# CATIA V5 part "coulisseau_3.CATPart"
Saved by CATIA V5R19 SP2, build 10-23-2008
Part number: coulisseau_3
Bounding box of the stored display mesh (mm): x -14.734 to 15.006, y -10 to 10, z -13.975 to 13.961
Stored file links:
  D:\Dropbox\IAO_2011\MMS_GR2\IAO_2011_1492_afeiguel\IAO_2011_1492_afeiguel\coulisseau_3.CATPart
  C:\Users\Nono\Desktop\projets ifma\IAO finis\assemblage_IAO.CATProduct
  D:\Dropbox\IAO_2011\MMS_GR2\IAO_2011_1492_afeiguel\IAO_2011_1492_afeiguel\bati_0.CATPart
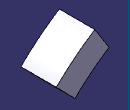
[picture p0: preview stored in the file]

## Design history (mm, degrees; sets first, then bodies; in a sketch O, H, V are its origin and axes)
External parameters (linked from other documents)
  External.e_rainure = 15 mm
  `External.rayon_glissière` = 125 mm
  `External.épaisseur` = 20 mm
Set1
  DatumSurface1: linked copy from another document
Body1 (main body)
  Sketch1 on yz-plane, origin (0, 0, 0), H (0, 1, 0), V (0, 0, 1)
    point P1 (0, 0)
    line L1 (-70.373, 0) -> (70, 0)
    point P2 (-70.373, 0)
    coincidence: P1 O, P2 H
    horizontal: L1 H
  Sketch2 on face of DatumSurface1, origin (0, -10, 0), H (1, 0, 0), V (0, 0, 1)
    arc A1 centre (-77.813, -97.8271) radius 132.5 from (15.006, -3.2708) to (-6.6817, 13.9611) ccw
    point P2 (-77.813, -97.8271)
    line L1 (15.006, -3.2708) -> (4.4982, -13.9753)
    line L2 (-6.6817, 13.9611) -> (-14.7343, 1.3058)
    arc A2 centre (-77.813, -97.8271) radius 117.5 from (4.4982, -13.9753) to (-14.7343, 1.3058) ccw
    point P6 (-77.813, -97.8271)
    reference projected point E1 (0, 0) from Sketch1.P1
    reference projected point E2 (0, 0) from Sketch1.P1
    reference projected point E3 (0, 0) from Sketch1.L1
    length L2 = 15 {= External.e_rainure}
    angle L1 L2 = 12
    distance P6 E1 = 125 {= `External.rayon_glissière`}
    distance E2 L1 = 13
    distance E3 A1 = 7.5 {= External.e_rainure /2}
    coincidence: L1 P2, L2 P2, P6 L2, P6 L1
  Pad1: profile Sketch2, direction (0, 1, 0), length 20 {= `External.épaisseur`}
